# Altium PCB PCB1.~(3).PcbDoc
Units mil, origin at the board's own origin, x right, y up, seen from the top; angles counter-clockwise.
Board outline 2435 x 2285 mil, 2 copper layers (Top Layer, Bottom Layer); 5 components, 8 nets, 44 pads, 0 vias.
Unrouted connection lines stored in the file: 2.
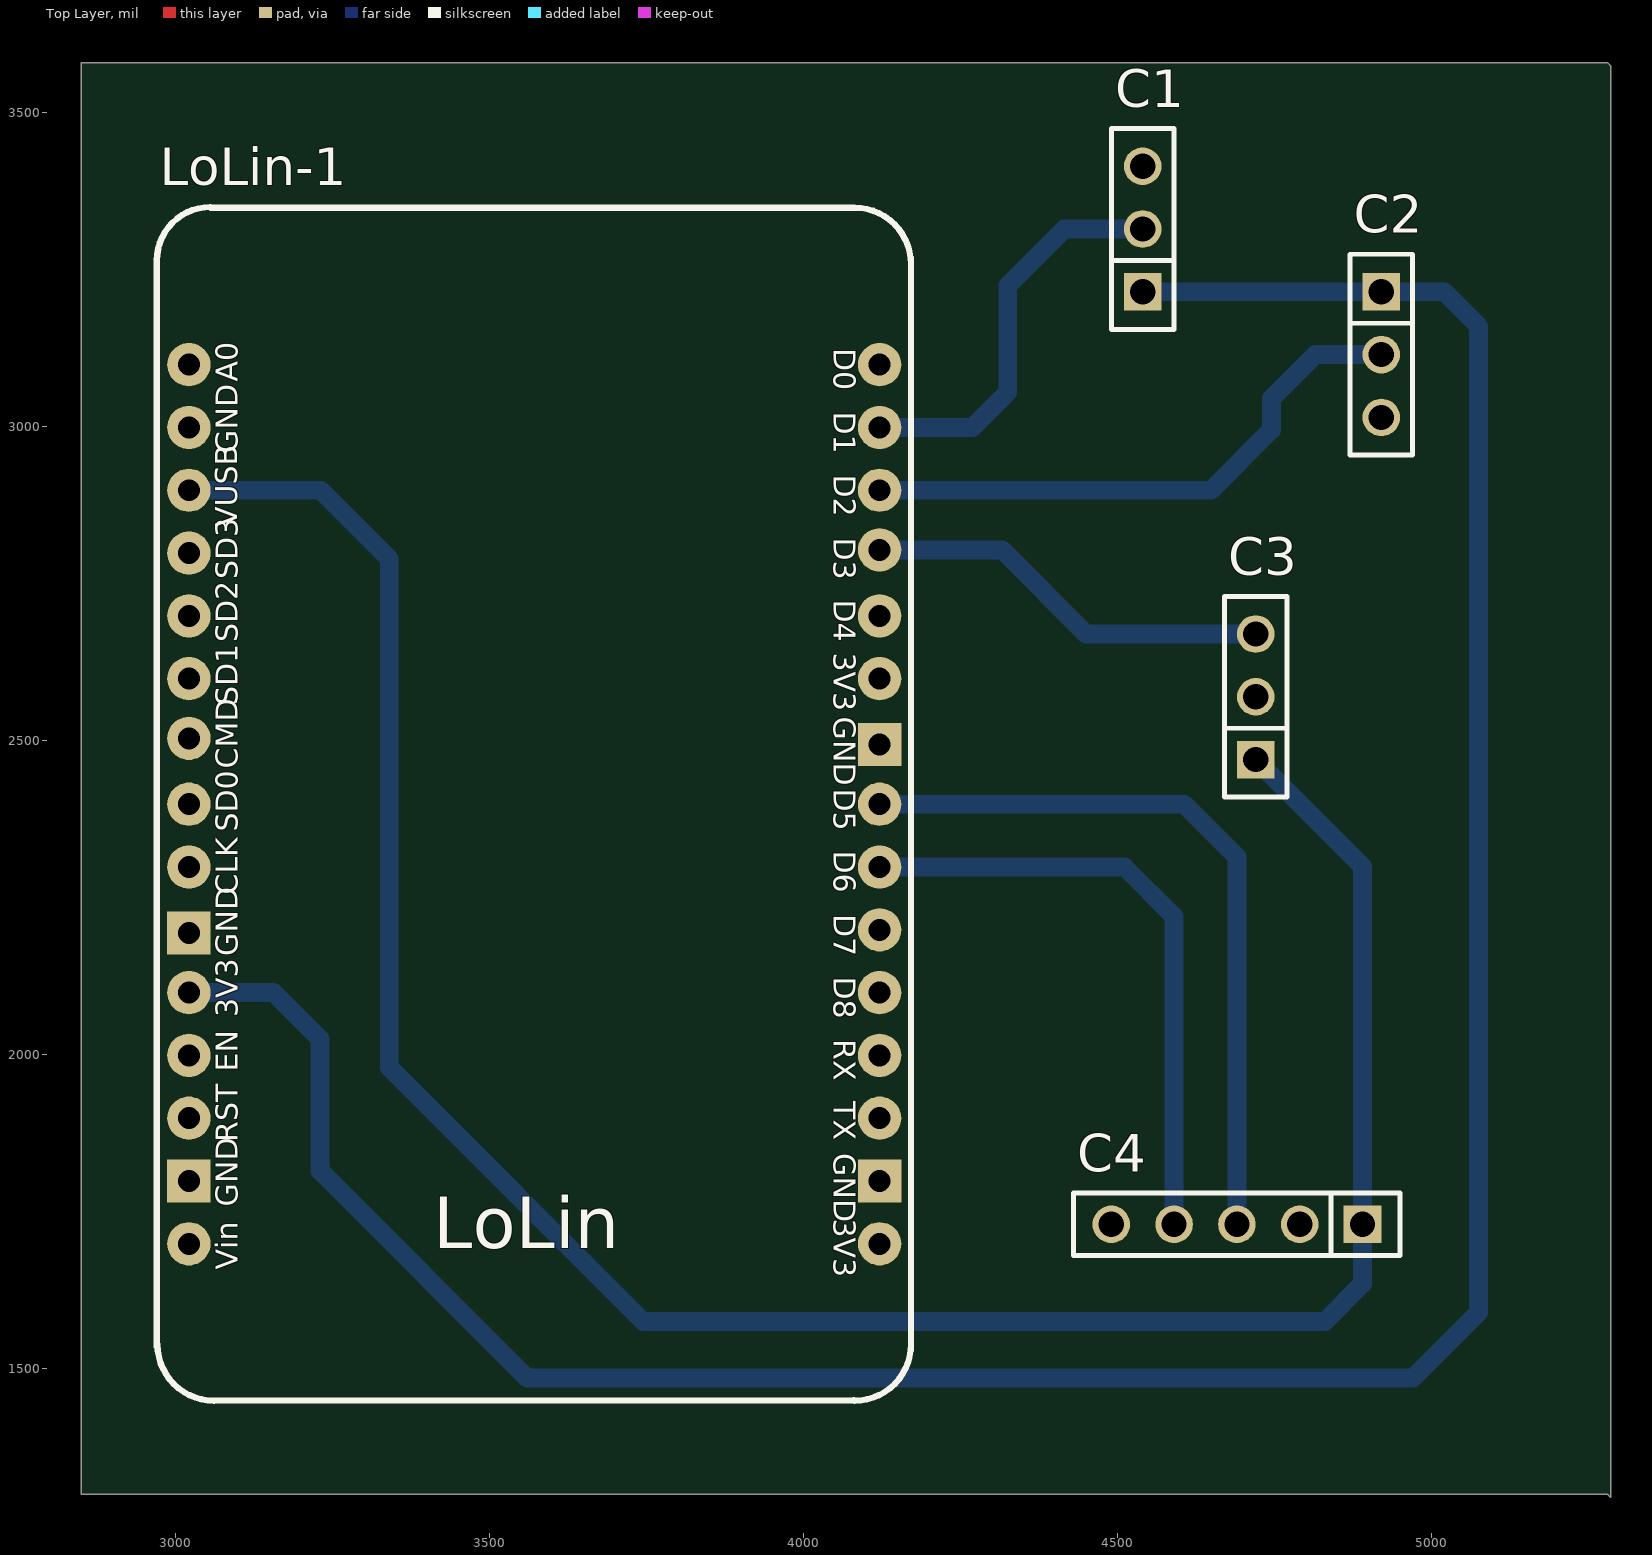
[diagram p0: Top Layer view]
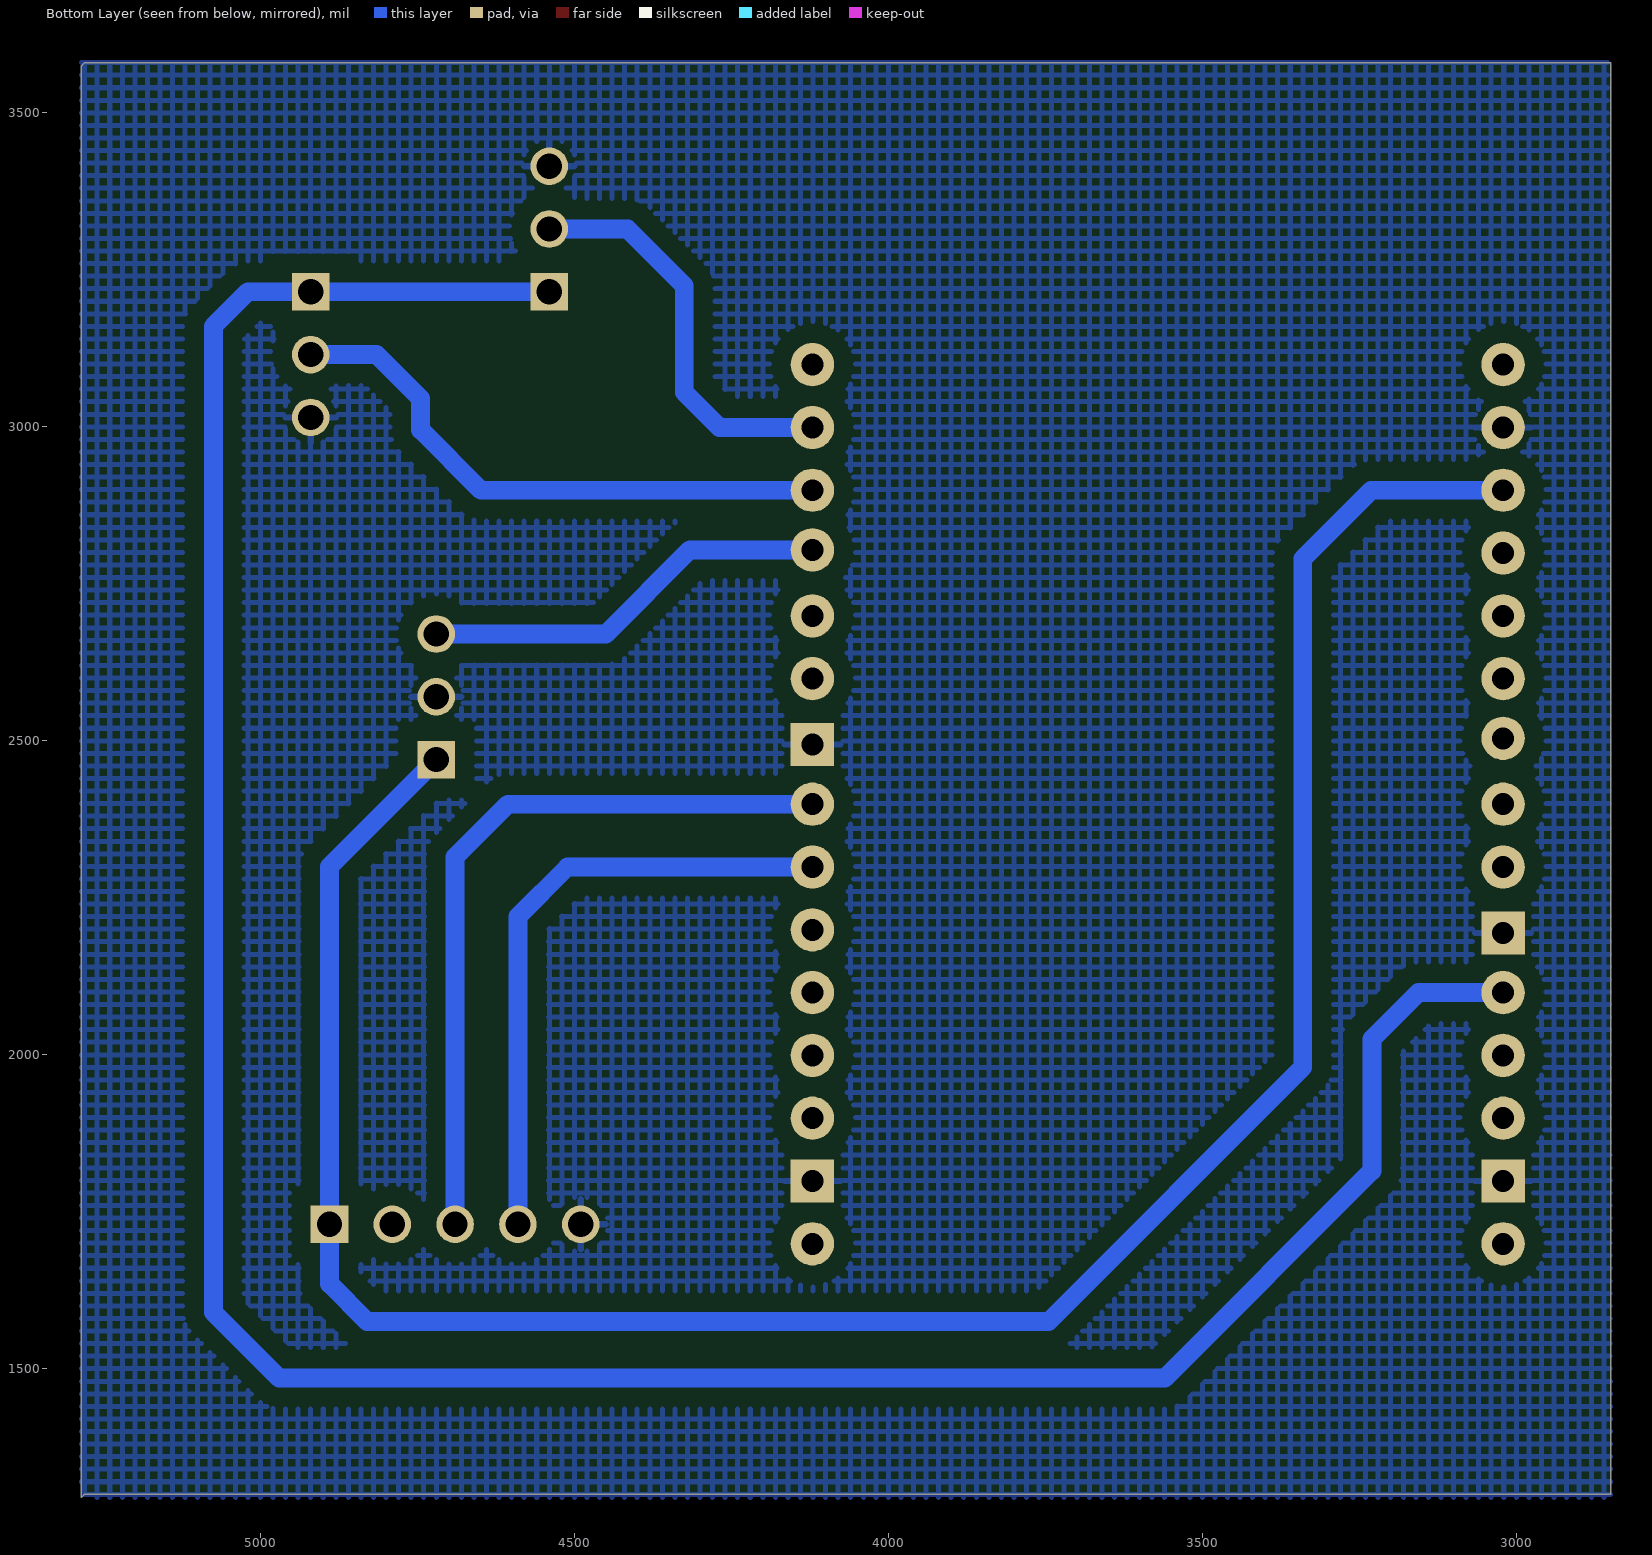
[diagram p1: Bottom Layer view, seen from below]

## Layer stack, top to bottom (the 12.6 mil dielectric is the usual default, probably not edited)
Top Solder: solder mask 0.4, Solder Resist, Dk 3.5
Top Layer: signal copper 1.4
Dielectric 1: dielectric 12.6, FR-4, Dk 4.8
Bottom Layer: signal copper 1.4
Bottom Solder: solder mask 0.4, Solder Resist, Dk 3.5

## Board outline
2850,1300 2850,3580 5280,3580 5285,3575 5285,1295 5280,1300

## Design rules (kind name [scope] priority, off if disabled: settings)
Clearance [All] p1: gap=30
PolygonConnect [All] p1: connectstyle=Relief reliefconductorwidth=10 reliefentries=4 polygonreliefangle="90 Angle" airgapwidth=10
RoutingVias [All] p1: holewidth=28 width=50 viastyle="Through Hole" minholewidth=28 minwidth=50 maxholewidth=28 maxwidth=50
SolderMaskExpansion [All] p1: expansion=4
Width [All] p1: maxlimit=30 minlimit=10 preferedwidth=20
30 further rules are at their usual default settings.

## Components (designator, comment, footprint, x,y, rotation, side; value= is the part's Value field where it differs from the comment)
C1 "JP3" JP3-C1T 4540,3215 r90 top
C2 "JP3" JP3-C1T 4920,3215 r270 top
C3 "JP3" JP3-C1T 4720,2470 r90 top
C4 "JP5" JP5-C1T 4890,1730 r180 top
LoLin-1 "NodeMCU V1.0 ESP-12E_1" "LoLin NodeMcu V3" 3070,3345 r0 top

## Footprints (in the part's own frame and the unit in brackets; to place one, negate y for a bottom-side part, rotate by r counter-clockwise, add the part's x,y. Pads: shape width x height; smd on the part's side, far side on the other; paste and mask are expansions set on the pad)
JP3-C1T [mm] "3 row, straight, gold plating"
  rect 1.52x1.52 hole 1.02: 1(0,0)
  round 1.52 hole 1.02: 2(2.54,0) 3(5.08,0)
  silkscreen extent -1.52,-1.27 6.6,1.27, body extent -1.52,-1.25 6.6,1.25, height 8.51
JP5-C1T [mm] "5 row, straight, gold plating"
  rect 1.52x1.52 hole 1.02: 1(0,0)
  round 1.52 hole 1.02: 2(2.54,0) 3(5.08,0) 4(7.62,0) 5(10.16,0)
  silkscreen extent -1.52,-1.27 11.68,1.27, body extent -1.52,-1.25 11.68,1.25, height 8.51
"LoLin NodeMcu V3" [mil]
  round 69 hole 35: 3V3(-49,-1246) 3V3(1051,-1646) 3V3(1051,-746) A0(-49,-246) CLK(-49,-1046) CMD(-49,-841) D0(1051,-246) D1(1051,-346) D2(1051,-446) D3(1051,-541) D4(1051,-646) D5(1051,-946) D6(1051,-1046) D7(1051,-1146) D8(1051,-1246) EN(-49,-1346) GND(-49,-346) RST(-49,-1446) RX(1051,-1346) SD0(-49,-946) SD1(-49,-746) SD2(-49,-646) SD3(-49,-546) TX(1051,-1446) VIN(-49,-1646) VUSB(-49,-446)
  rect 69x69 hole 35: GND(-49,-1546) GND(-49,-1151) GND(1051,-1546) GND(1051,-851)
  silkscreen extent -100,-1896 1101,5

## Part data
C1 C2 C3 C4: "WR-PHD 2.54 mm Angled Socket Header"
LoLin-1: "LoLin NodeMCU V3"

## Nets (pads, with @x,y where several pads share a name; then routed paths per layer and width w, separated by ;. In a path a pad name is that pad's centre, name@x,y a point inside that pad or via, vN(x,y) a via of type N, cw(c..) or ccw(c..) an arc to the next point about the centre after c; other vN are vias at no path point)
3.3V: C1.1 C2.1 LoLin-1.3V3 | length 4602.6
  Bottom Layer w30: LoLin-1.3V3@3021,2099 3156,2099 3230,2025 3230,1815 3560,1485 4970,1485 5075,1590 5075,3160 5020,3215 C2.1 C1.1
DHT1: C1.2 LoLin-1.D1 | length 649.5
  Bottom Layer w30: LoLin-1.D1 4269,2999 4325,3055 4325,3225 4415,3315 C1.2
DHT2: C2.2 LoLin-1.D2 | length 917.8
  Bottom Layer w30: LoLin-1.D2 4649,2899 4745,2995 4745,3045 4815,3115 C2.2
GND: C1.3 C2.3 C3.2 C4.5 LoLin-1.GND
NetC4_3: C4.3 LoLin-1.D5 | length 1188.8
  Bottom Layer w30: LoLin-1.D5 4606,2399 4690,2315 C4.3
NetC4_4: C4.4 LoLin-1.D6 | length 991.7
  Bottom Layer w30: LoLin-1.D6 4511,2299 4590,2220 C4.4
RELAY: C3.3 LoLin-1.D3 | length 654.5
  Bottom Layer w30: LoLin-1.D3 4316,2804 4450,2670 C3.3
VCC: C3.1 C4.1 LoLin-1.VUSB | length 3822.2
  Bottom Layer w30: LoLin-1.VUSB 3231,2899 3340,2790 3340,1980 3745,1575 4830,1575 4890,1635 C4.1 4890,2300 C3.1
pads on no net: C4.2 LoLin-1.A0 LoLin-1.CLK LoLin-1.CMD LoLin-1.D0 LoLin-1.D4 LoLin-1.D7 LoLin-1.D8 LoLin-1.EN LoLin-1.RST LoLin-1.RX LoLin-1.SD0 LoLin-1.SD1 LoLin-1.SD2 LoLin-1.SD3 LoLin-1.TX LoLin-1.VIN

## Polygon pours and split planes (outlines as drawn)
GND on Mechanical 1 "Bottom Layer-No Net" (hatched 90Degree grid 20 track 8, remove dead copper): 2850,3580 5290,3580 5300,3570 5280,3550 5280,1300 2860,1300
GND on Mechanical 1 "Bottom Layer-No Net" (hatched 90Degree grid 20 track 8, remove dead copper): 2850,3580 5280,3580 5280,1300 2850,1300
GND on Bottom Layer "Bottom Layer-No Net" (hatched 90Degree grid 20 track 8, remove dead copper, pour order 0): 2855,3585 2860,3580 5285,3580 5285,1305 5280,1300 5275,1295 2850,1295

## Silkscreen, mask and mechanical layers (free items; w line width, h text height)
Mechanical 1:
  lines w10: 2850,1300 5280,1300 5285,1295 5285,3575 5280,3580 2850,3580 2850,1350 2850,1300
